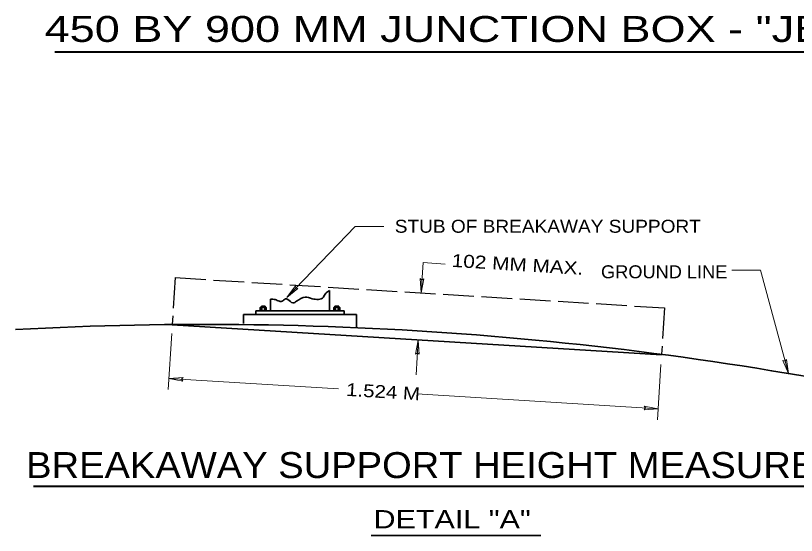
# Model space of a CAD drawing. Extents: x 312583 to 312853, y 144419 to 144586.
# Drawn here: x 312720.25 to 312766.04, y 144505.2 to 144535.67 of the extents above; entities that cross this region are included whole.
import ezdxf
from ezdxf.enums import TextEntityAlignment as Align

# ---------------------------------------------------------------- set-up
doc = ezdxf.new("R2010")
doc.units = 0
doc.header["$LTSCALE"] = 0.3
doc.linetypes.add('LONG_DASHED', pattern=[7.5, 6, -1.5])
doc.layers.add('1', color=7, linetype='Continuous', lineweight=40)
doc.layers.add('2', color=7, linetype='Continuous', lineweight=13)

msp = doc.modelspace()

# ---------------------------------------------------------------- linework, layer by layer
at = {"layer": '1', "lineweight": 13}
for p, q in [((312740.1644, 144523.3096), (312736.1624, 144519.1542)), ((312740.1644, 144523.3096), (312741.8434, 144523.3096)), ((312744.1434, 144521.1936), (312744.0284, 144519.4226)), ((312744.1434, 144521.1936), (312745.4314, 144521.1092)), ((312762.2444, 144520.7566), (312763.9234, 144520.7566)), ((312763.9234, 144520.7566), (312765.5717, 144514.6922)), ((312729.1934, 144513.7569), (312729.4004, 144517.0306)), ((312743.737, 144514.6232), (312743.8597, 144516.6549)), ((312757.8897, 144511.9859), (312758.089, 144515.2289)), ((312729.2317, 144514.4009), (312739.183, 144513.7876)), ((312757.928, 144512.6299), (312743.7677, 144513.5039))]:
    msp.add_line(p, q, dxfattribs=at)
at = {"layer": '1', "linetype": 'LONG_DASHED', "lineweight": 25}
for p, q in [((312729.5997, 144520.3119), (312729.431, 144517.5672)), ((312729.5997, 144520.3119), (312758.296, 144518.5409)), ((312758.296, 144518.5409), (312758.1274, 144515.8192))]:
    msp.add_line(p, q, dxfattribs=at)
at = {"layer": '1', "lineweight": 35}
for p, q in [((312738.654, 144518.3722), (312738.654, 144519.5606)), ((312735.204, 144518.3722), (312735.204, 144519.0469)), ((312734.5984, 144518.5639), (312734.5984, 144518.3722)), ((312734.6444, 144518.5869), (312734.8974, 144518.5869)), ((312734.6597, 144518.6406), (312734.6597, 144518.5869)), ((312734.6597, 144518.6406), (312734.882, 144518.6406)), ((312734.6827, 144518.5639), (312734.6827, 144518.3722)), ((312734.8514, 144518.5639), (312734.8514, 144518.3722)), ((312734.882, 144518.6406), (312734.882, 144518.5869)), ((312734.9357, 144518.5639), (312734.9357, 144518.3722)), ((312738.9147, 144518.5639), (312738.9147, 144518.3722)), ((312738.953, 144518.5869), (312739.206, 144518.5869)), ((312738.9684, 144518.6406), (312738.9684, 144518.5869)), ((312738.9684, 144518.6406), (312739.1984, 144518.6406)), ((312738.999, 144518.5639), (312738.999, 144518.3722)), ((312739.1677, 144518.5639), (312739.1677, 144518.3722)), ((312739.1984, 144518.6406), (312739.1984, 144518.5869)), ((312739.252, 144518.5639), (312739.252, 144518.3722)), ((312733.617, 144518.1422), (312733.617, 144517.6209)), ((312734.3377, 144518.3722), (312734.3377, 144518.1422)), ((312734.3377, 144518.3722), (312739.5127, 144518.3722)), ((312739.5127, 144518.3722), (312739.5127, 144518.1422)), ((312729.431, 144517.5442), (312758.1274, 144515.7809)), ((312741.103, 144505.2048), (312751.0519, 144505.2048))]:
    msp.add_line(p, q, dxfattribs=at)
at = {"layer": '1'}
msp.add_line((312721.3052, 144508.0989), (312773.4318, 144508.0989), dxfattribs=at)
at = {"layer": '1', "lineweight": 13}
for points in [[(312744.1817, 144520.2429), (312744.0284, 144519.4226), (312743.967, 144520.2582), (312744.0744, 144520.1662)], [(312736.8064, 144519.6756), (312736.1624, 144519.1542), (312736.653, 144519.8289), (312736.676, 144519.6909)], [(312743.7064, 144515.8346), (312743.8597, 144516.6549), (312743.921, 144515.8269), (312743.8137, 144515.9112)], [(312765.4567, 144515.5202), (312765.5717, 144514.6922), (312765.2497, 144515.4589), (312765.38, 144515.4129)], [(312730.052, 144514.2476), (312729.2317, 144514.4009), (312730.0674, 144514.4622), (312729.983, 144514.3549)], [(312757.1077, 144512.7832), (312757.928, 144512.6299), (312757.1, 144512.5686), (312757.1844, 144512.6759)]]:
    msp.add_lwpolyline(points, close=True, dxfattribs=at)
at = {"layer": '1', "lineweight": 35}
msp.add_lwpolyline([(312733.617, 144518.1422), (312740.2334, 144518.1422), (312740.2334, 144517.3832)], dxfattribs=at)
for centre, radius, start, end in [((312734.6429, 144518.5416), 0.0467, 25.60064, 154.39936), ((312734.7692, 144518.4413), 0.1469, 55.04559, 124.95441), ((312734.8955, 144518.5416), 0.0467, 25.60064, 154.39936), ((312738.9554, 144518.5416), 0.0467, 25.60064, 154.39936), ((312739.0817, 144518.4413), 0.1469, 55.04559, 124.95441), ((312739.208, 144518.5416), 0.0467, 25.60064, 154.39936), ((312731.3674, 144313.1134), 204.4606, 77.47167, 93.11775)]:
    msp.add_arc(centre, radius, start, end, dxfattribs=at)
msp.add_spline([(312735.204, 144519.0469), (312735.4724, 144519.0239), (312735.7177, 144518.9319), (312735.9247, 144518.9549), (312736.0704, 144519.0622), (312736.216, 144519.0316), (312736.5074, 144518.8399), (312736.722, 144518.9242), (312737.228, 144519.1772), (312737.642, 144519.0776), (312738.2937, 144519.1696), (312738.4394, 144519.3996), (312738.654, 144519.5606)], degree=3, dxfattribs=at)
at = {"layer": '2', "lineweight": 40}
msp.add_line((312722.5394, 144533.5554), (312768.1782, 144533.5554), dxfattribs=at)

# ---------------------------------------------------------------- texts
at = {"layer": '1'}
for s, width, p in [('STUB OF BREAKAWAY SUPPORT', 1.1, (312742.4818, 144522.9433)), ('GROUND LINE', 1.05, (312754.5777, 144520.2754))]:
    msp.add_text(s, height=0.76, dxfattribs=dict(at, width=width)).set_placement(p)
at = {"layer": '1', "width": 1.2}
msp.add_text('102 MM MAX.', height=0.76, rotation=356.473, dxfattribs=at).set_placement((312745.804, 144520.9477))
msp.add_text('1.524 M', height=0.7475, rotation=356.473, dxfattribs=at).set_placement((312741.7743, 144513.2538), align=Align.CENTER)
at = {"layer": '1'}
for s, height, width, p in [('BREAKAWAY SUPPORT HEIGHT MEASUREMENT', 1.52, 1.1, (312747.2009, 144508.5649)), ('DETAIL "A"', 1.07, 1.25, (312745.8472, 144505.6157))]:
    msp.add_text(s, height=height, dxfattribs=dict(at, width=width)).set_placement(p, align=Align.CENTER)
at = {"layer": '2', "width": 1.3}
msp.add_text('450 BY 900 MM JUNCTION BOX - "JB"', height=1.52, dxfattribs=at).set_placement((312745.2779, 144534.1286), align=Align.CENTER)

doc.saveas('drawing.dxf')
